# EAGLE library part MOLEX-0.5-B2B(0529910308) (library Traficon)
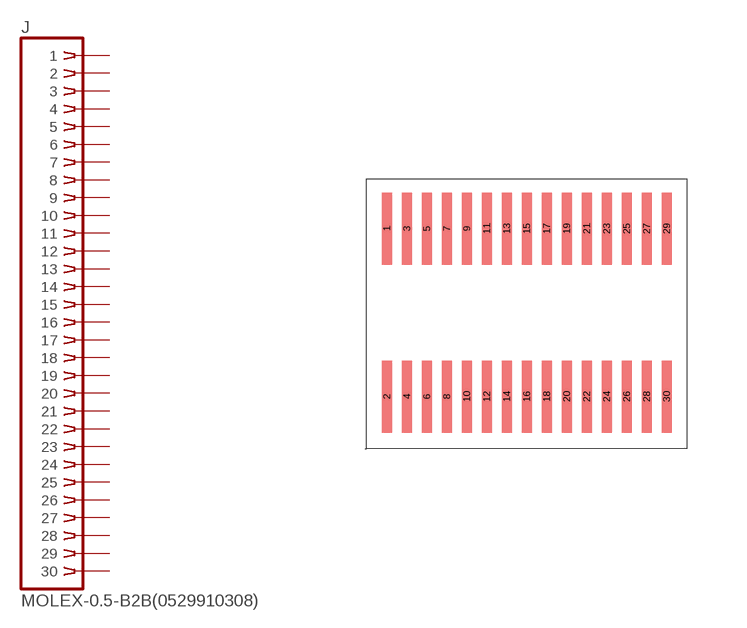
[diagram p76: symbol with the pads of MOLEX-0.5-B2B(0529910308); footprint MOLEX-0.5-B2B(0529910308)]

Designator prefix J

## MOLEX-0.5-B2B(0529910308)  [MOLEX-0.5-B2B(0529910308)]
1  1  pas
2  2  pas
3  3  pas
4  4  pas
5  5  pas
6  6  pas
7  7  pas
8  8  pas
9  9  pas
10  10  pas
11  11  pas
12  12  pas
13  13  pas
14  14  pas
15  15  pas
16  16  pas
17  17  pas
18  18  pas
19  19  pas
20  20  pas
21  21  pas
22  22  pas
23  23  pas
24  24  pas
25  25  pas
26  26  pas
27  27  pas
28  28  pas
29  29  pas
30  30  pas

## Footprint MOLEX-0.5-B2B(0529910308) (pad centres in mm)
smd 0.25 x 1.8: 1 -3.5,2; 2 -3.5,-2.2; 3 -3,2; 4 -3,-2.2; 5 -2.5,2; 6 -2.5,-2.2; 7 -2,2; 8 -2,-2.2; 9 -1.5,2; 10 -1.5,-2.2; 11 -1,2; 12 -1,-2.2; 13 -0.5,2; 14 -0.5,-2.2; 15 0,2; 16 0,-2.2; 17 0.5,2; 18 0.5,-2.2; 19 1,2; 20 1,-2.2; 21 1.5,2; 22 1.5,-2.2; 23 2,2; 24 2,-2.2; 25 2.5,2; 26 2.5,-2.2; 27 3,2; 28 3,-2.2; 29 3.5,2; 30 3.5,-2.2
